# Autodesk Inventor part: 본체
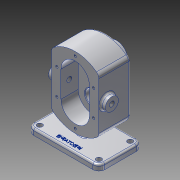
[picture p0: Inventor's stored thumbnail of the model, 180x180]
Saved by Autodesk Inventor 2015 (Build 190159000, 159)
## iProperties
Created: 2019-03
Part Number: 본체
Material: 알루미늄 6061
Document SubType Name: Modeling
Designer: now
Density: 2.7 g/cm^3
Appearance: 알루미늄 - 평지
Mass: 1186.71 g
Surface Area: 720.452 cm^2
Volume: 439.521 cm^3
Author: now
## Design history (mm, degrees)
sketch "스케치1"
  geometry: L1 (-60, 36.5)-(60, 36.5); L2 (60, 36.5)-(60, -36.5); L3 (60, -36.5)-(-60, -36.5); L4 (-60, -36.5)-(-60, 36.5); L5 (-60, 36.5)-(60, -36.5); L6 (60, 36.5)-(-60, -36.5); 1 further point
  constraints: 12 end point, 2 midpoint, 2 parallel, 1 horizontal, 1 perpendicular
  dimensions: "d0" = 120 distance of L2.end L3.end; "d1" = 73 distance of L1.end L2.end
extrude "돌출1" new body sketch "스케치1" distance "d2" = 10; taper "d3" = 0 deg
fillet "모깎기1" dims "d4" = 10
sketch "스케치2"
  geometry: L1 (-60, -26.5)-(-60, 26.5) reference; L2 (-50, 36.5)-(50, 36.5) reference; L3 (60, 26.5)-(60, -26.5) reference; L4 (50, -36.5)-(-50, -36.5) reference; L5 (-6, 36.5)-(6, 36.5); L6 (6, 36.5)-(6, -6.5); L7 (6, -6.5)-(-6, -6.5); L8 (-6, -6.5)-(-6, 36.5); A1 r 10 centre (-50, -26.5) between (-60, -26.5) and (-50, -36.5) reference; A2 r 10 centre (-50, 26.5) between (-50, 36.5) and (-60, 26.5) reference; A3 r 10 centre (50, 26.5) between (60, 26.5) and (50, 36.5) reference; A4 r 10 centre (50, -26.5) between (50, -36.5) and (60, -26.5) reference; 2 further points
  constraints: 8 end point, 2 parallel, 1 horizontal, 1 midpoint, 1 perpendicular, 1 point on line, 1 vertical alignment
  dimensions: "d5" = 12 distance of L6.end L7.end; "d6" = 43 distance of L5.end L6.end
extrude "돌출2" join sketch "스케치2" distance "d7" = 68; taper "d8" = 0 deg
sketch "스케치3"
  geometry: L1 (60, 0)-(-60, 0) reference; L2 (-60, 0)-(-60, 10) reference; L3 (-60, 10)-(-6, 10) reference; L4 (-6, 10)-(-6, 78) reference; L5 (-6, 78)-(6, 78) reference; L6 (6, 78)-(6, 10) reference; L7 (6, 10)-(60, 10) reference; L8 (60, 10)-(60, 0) reference; L9 (40, 122.721)-(40, 33.279); L10 (-40, 122.721)-(-40, 33.279); L11 (0, 138)-(0, 18); A1 r 60 centre (0, 78) between (-40, 33.279) and (40, 33.279); A2 r 60 centre (0, 78) between (40, 122.721) and (-40, 122.721); 2 further points
  constraints: 6 end point, 6 point on circle, 2 centre point, 2 midpoint, 2 vertical, 1 coincident, 1 parallel, 1 other
  dimensions: "d13" = 80 distance between parallel lines of L10 L9; "d14" = 60 radius of A2
extrude "돌출3" join sketch "스케치3" distance "d15" = 36.5; taper "d17" = 0 deg; dims "d16" = 16.5, "d18" = 0
fillet "모깎기2" dims "d19" = 10
sketch "스케치4"
  geometry: L1 (-40, 38)-(-40, 118) reference; L2 (40, 118)-(40, 38) reference; L3 (60, 0)-(-60, 0) reference; L4 (-60, 0)-(-60, 10) reference; L5 (-60, 10)-(60, 10) reference; L6 (60, 10)-(60, 0) reference; L7 (-24, 100)-(-24, 56); L8 (24, 100)-(24, 56); L9 (40, 118)-(40, 38) reference; A1 r 24 centre (0, 100) between (24, 100) and (-24, 100); A2 r 24 centre (0, 56) between (-24, 56) and (24, 56); A3 r 10 centre (30, 38) between (36, 30) and (40, 38) reference; A4 r 60 centre (0, 78) between (-36, 30) and (36, 30) reference; A5 r 10 centre (-30, 38) between (-40, 38) and (-36, 30) reference; A6 r 10 centre (-30, 118) between (-36, 126) and (-40, 118) reference; A7 r 60 centre (0, 78) between (36, 126) and (-36, 126) reference; A8 r 10 centre (30, 118) between (40, 118) and (36, 126) reference; 2 further points
  constraints: 4 end point, 4 point on circle, 3 vertical alignment, 2 centre point, 2 tangent, 2 vertical, 1 horizontal alignment, 1 midpoint
  dimensions: "d20" = 48 diameter of A1; "d21" = 48 diameter of A2; "d22" = 44 distance of L8.start L8.end
extrude "돌출4" cut sketch "스케치4" distance "d23" = 29; taper "d24" = 0 deg
sketch "스케치5"
  geometry: L1 (-24, 100)-(-24, 56) reference; L2 (24, 56)-(24, 100) reference; L3 (60, 0)-(-60, 0) reference; L4 (-60, 0)-(-60, 10) reference; L5 (-60, 10)-(-6, 10) reference; L6 (-6, 10)-(-6, 18.301) reference; L7 (-40, 38)-(-40, 118) reference; L8 (40, 118)-(40, 38) reference; L9 (6, 18.301)-(6, 10) reference; L10 (6, 10)-(60, 10) reference; L11 (60, 10)-(60, 0) reference; A1 r 24 centre (0, 56) between (-24, 56) and (24, 56) reference; A2 r 24 centre (0, 100) between (24, 100) and (-24, 100) reference; A3 r 60 centre (0, 78) between (-36, 30) and (-6, 18.301) reference; A4 r 10 centre (-30, 38) between (-40, 38) and (-36, 30) reference; A5 r 10 centre (-30, 118) between (-36, 126) and (-40, 118) reference; A6 r 60 centre (0, 78) between (36, 126) and (-36, 126) reference; A7 r 10 centre (30, 118) between (40, 118) and (36, 126) reference; A8 r 10 centre (30, 38) between (36, 30) and (40, 38) reference; A9 r 60 centre (0, 78) between (6, 18.301) and (36, 30) reference; 1 further point
hole "구멍1" sketch "스케치5" at (0, 56) diameter "d25" = 25; stored, may be unused: countersink angle "d29" = 90 deg, drill point angle "d31" = 0 deg; dims "d26" = 6, "d27" = 4, "d28" = 2, "d30" = 15
sketch "스케치6"
  geometry: L1 (40, -38)-(40, -118) reference; L2 (-40, -118)-(-40, -38) reference; L3 (24, -100)-(24, -56) reference; L4 (-24, -56)-(-24, -100) reference; L5 (-6, -18.301)-(-6, -10) reference; L6 (-6, -10)-(-50, -10) reference; L7 (-50, 0)-(-50, -10) reference; L8 (-50, 0)-(50, 0) reference; L9 (50, 0)-(50, -10) reference; L10 (50, -10)-(6, -10) reference; L11 (6, -10)-(6, -18.301) reference; C1 r 12.5 at (0, -56) reference; C2 r 19 at (0, -100); A1 r 10 centre (30, -38) between (40, -38) and (36, -30) reference; A2 r 10 centre (30, -118) between (36, -126) and (40, -118) reference; A3 r 60 centre (0, -78) between (-36, -126) and (36, -126) reference; A4 r 10 centre (-30, -118) between (-40, -118) and (-36, -126) reference; A5 r 10 centre (-30, -38) between (-36, -30) and (-40, -38) reference; A6 r 24 centre (0, -100) between (-24, -100) and (24, -100) reference; A7 r 24 centre (0, -56) between (24, -56) and (-24, -56) reference; A8 r 60 centre (0, -78) between (-6, -18.301) and (-36, -30) reference; A9 r 60 centre (0, -78) between (36, -30) and (6, -18.301) reference; 1 further point
  constraints: 1 centre point, 1 coincident
  dimensions: "d33" = 38 diameter of C2
extrude "돌출5" join sketch "스케치6" distance "d34" = 17; taper "d35" = 0 deg
sketch "스케치7"
  geometry: C1 r 19 at (0, 0) reference; 1 further point
hole "구멍2" sketch "스케치7" at (0, 0) diameter "d36" = 17; stored, may be unused: countersink angle "d40" = 90 deg, drill point angle "d42" = 0 deg; dims "d37" = 6, "d38" = 28, "d39" = 7.3, "d41" = 15
sketch "스케치8"
  geometry: L1 (-24, 100)-(-24, 56) reference; L2 (24, 56)-(24, 100) reference; L3 (60, 0)-(-60, 0) reference; L4 (-60, 0)-(-60, 10) reference; L5 (-60, 10)-(-6, 10) reference; L6 (-6, 10)-(-6, 18.301) reference; L7 (-40, 38)-(-40, 118) reference; L8 (40, 118)-(40, 38) reference; L9 (6, 18.301)-(6, 10) reference; L10 (6, 10)-(60, 10) reference; L11 (60, 10)-(60, 0) reference; C1 r 8.5 at (0, 100) reference; C2 r 12.5 at (0, 56) reference; A1 r 24 centre (0, 56) between (-24, 56) and (24, 56) reference; A2 r 24 centre (0, 100) between (24, 100) and (-24, 100) reference; A3 r 60 centre (0, 78) between (-36, 30) and (-6, 18.301) reference; A4 r 10 centre (-30, 38) between (-40, 38) and (-36, 30) reference; A5 r 10 centre (-30, 118) between (-36, 126) and (-40, 118) reference; A6 r 60 centre (0, 78) between (36, 126) and (-36, 126) reference; A7 r 10 centre (30, 118) between (40, 118) and (36, 126) reference; A8 r 10 centre (30, 38) between (36, 30) and (40, 38) reference; A9 r 60 centre (0, 78) between (6, 18.301) and (36, 30) reference; 1 further point
hole "구멍3" sketch "스케치8" at (0, 100) diameter "d43" = 17; stored, may be unused: countersink angle "d47" = 90 deg, drill point angle "d49" = 0 deg; dims "d44" = 6, "d45" = 25, "d46" = 15, "d48" = 15
sketch "스케치9"
  geometry: L1 (-60, -26.5)-(-60, 26.5) reference; L2 (-50, 36.5)-(-6, 36.5) reference; L3 (-6, -6.5)-(-6, 36.5) reference; L4 (6, -6.5)-(-6, -6.5) reference; L5 (6, 36.5)-(6, -6.5) reference; L6 (-6, 36.5)-(6, 36.5) reference; L7 (50, -36.5)-(-50, -36.5) reference; L8 (60, 26.5)-(60, -26.5) reference; L9 (6, 36.5)-(50, 36.5) reference; A1 r 10 centre (-50, -26.5) between (-60, -26.5) and (-50, -36.5) reference; A2 r 10 centre (-50, 26.5) between (-50, 36.5) and (-60, 26.5) reference; A3 r 10 centre (50, -26.5) between (50, -36.5) and (60, -26.5) reference; A4 r 10 centre (50, 26.5) between (60, 26.5) and (50, 36.5) reference; 1 further point
hole "구멍4" sketch "스케치9" at (-50, -26.5), (50, -26.5), (50, 26.5), (-50, 26.5) diameter "d50" = 9; stored, may be unused: countersink angle "d54" = 90 deg, drill point angle "d56" = 0 deg; dims "d51" = 6, "d52" = 25, "d53" = 15, "d55" = 15
sketch "스케치10"
  geometry: L1 (0, 0)-(-80, 0) reference; L2 (-80, 53)-(-80, 0) reference; L3 (-80, 53)-(0, 53) reference; L4 (0, 53)-(0, 0) reference; L5 (28, 53)-(38, 53) reference; L6 (38, 53)-(38, -20) reference; L7 (38, -20)-(28, -20) reference; L8 (28, -20)-(28, 53) reference; C1 r 11 at (-40, 14); 2 further points
  constraints: 1 centre point, 1 midpoint, 1 vertical alignment
  dimensions: "d60" = 22 diameter of C1; "d61" = 14 distance from line of C1.centre L1
extrude "돌출6" join sketch "스케치10" distance "d58" = 8; taper "d59" = 0 deg
sketch "스케치11"
  geometry: L1 (78, -19.969)-(68, -19.969) reference; L2 (68, -19.969)-(68, 24.969) reference; L3 (68, 24.969)-(78, 24.969) reference; L4 (78, 24.969)-(78, -19.969) reference; L5 (68, -28.031)-(78, -28.031) reference; L6 (78, -28.031)-(78, -34) reference; L7 (78, -34)-(68, -34) reference; L8 (68, -34)-(68, -28.031) reference; L9 (68, 39)-(78, 39) reference; L10 (78, 39)-(78, 33.031) reference; L11 (78, 33.031)-(68, 33.031) reference; L12 (68, 33.031)-(68, 39) reference; C1 r 11 at (0, 0) reference; 1 further point
hole "구멍5" sketch "스케치11" at (0, 0) diameter "d62" = 8.376; stored, may be unused: countersink angle "d66" = 90 deg, drill point angle "d68" = 0 deg; dims "d63" = 20, "d64" = 25, "d65" = 15, "d67" = 27.3
sketch "스케치12"
  geometry: L1 (-24, 100)-(-24, 56) reference; L2 (24, 56)-(24, 100) reference; L3 (-40, 38)-(-40, 118) reference; L4 (40, 118)-(40, 38) reference; L5 (60, 0)-(-60, 0) reference; L6 (-60, 0)-(-60, 10) reference; L7 (-60, 10)-(60, 10) reference; L8 (60, 10)-(60, 0) reference; L9 (-31, 100)-(31, 100); L10 (-31, 56)-(31, 56); L11 (0, 131)-(0, 25); A1 r 24 centre (0, 56) between (-24, 56) and (24, 56) reference; A2 r 24 centre (0, 100) between (24, 100) and (-24, 100) reference; A3 r 10 centre (30, 38) between (36, 30) and (40, 38) reference; A4 r 60 centre (0, 78) between (-36, 30) and (36, 30) reference; A5 r 10 centre (-30, 38) between (-40, 38) and (-36, 30) reference; A6 r 10 centre (-30, 118) between (-36, 126) and (-40, 118) reference; A7 r 60 centre (0, 78) between (36, 126) and (-36, 126) reference; A8 r 10 centre (30, 118) between (40, 118) and (36, 126) reference; 5 further points
  constraints: 6 end point, 3 coincident, 3 midpoint, 2 horizontal, 1 vertical
  dimensions: "d71" = 62 distance of L10.start L10.end; "d72" = 62 distance of L9.start L9.end; "d73" = 31 distance from line of L9 L11.start
hole "구멍6" sketch "스케치12" at (0, 131), (-31, 100), (-31, 56), (0, 25), (31, 56), (31, 100) diameter "d74" = 4.134; stored, may be unused: countersink angle "d78" = 90 deg, drill point angle "d80" = 118 deg; dims "d75" = 10, "d76" = 25, "d77" = 15, "d79" = 12
fillet "모깎기3" dims "d81" = 3
fillet "모깎기5" dims "d83" = 3
chamfer "모따기1" distance "d85" = 1; stored, may be unused: second distance "d86" = 2, angle "d87" = 45 deg
fillet "모깎기9" dims "d90" = 3
sketch "스케치13"
  geometry: L1 (50, -36.5)-(-50, -36.5) reference; L2 (-60, 26.5)-(-60, -26.5) reference; L3 (6, 36.5)-(6, -6.5) reference; L4 (-6, -6.5)-(-6, 36.5) reference; L5 (-6, 36.5)-(6, 36.5) reference; L6 (6, -6.5)-(-6, -6.5) reference; L7 (-60, -26.5)-(-60, 26.5) reference; L8 (-50, 36.5)-(-6, 36.5) reference; L9 (6, 36.5)-(50, 36.5) reference; L10 (60, 26.5)-(60, -26.5) reference; L11 (50, -36.5)-(-50, -36.5) reference; C1 r 4.5 at (50, 26.5) reference; C2 r 4.5 at (-50, -26.5) reference; C3 r 4.5 at (50, -26.5) reference; C4 r 4.5 at (-50, 26.5) reference; A1 r 10 centre (-50, -26.5) between (-60, -26.5) and (-50, -36.5) reference; A2 r 10 centre (-50, 26.5) between (-50, 36.5) and (-60, 26.5) reference; A3 r 10 centre (50, 26.5) between (60, 26.5) and (50, 36.5) reference; A4 r 10 centre (50, -26.5) between (50, -36.5) and (60, -26.5) reference; 2 further points
  constraints: 1 other
  dimensions: "d91" = 10 distance from line of point (0, -26.5) L1; "d92" = 60 distance from line of point (0, -26.5) L2
feature "엠보싱1" sketch "스케치13" dims "d0" = 120, "d1" = 73, "d8" = 0, "d93" = 0.5, "d94" = 0
fillet "모깎기12" dims "d97" = 0.5
chamfer "모따기2" distance "d98" = 0.7; stored, may be unused: second distance "d99" = 2, angle "d100" = 30 deg
fillet "모깎기13" dims "d101" = 3
node "솔리드1"
mirror "대칭1"
node "투영된 루프1"
node "절단 모서리 투영1"
node "절단 모서리 투영2"
node "절단 모서리 투영3"
node "절단 모서리 투영4"
node "절단 모서리 투영5"
node "절단 모서리 투영6"
node "절단 모서리 투영7"
node "절단 모서리 투영8"
node "절단 모서리 투영9"
node "절단 모서리 투영10"
node "절단 모서리 투영11"
node "절단 모서리 투영12"
